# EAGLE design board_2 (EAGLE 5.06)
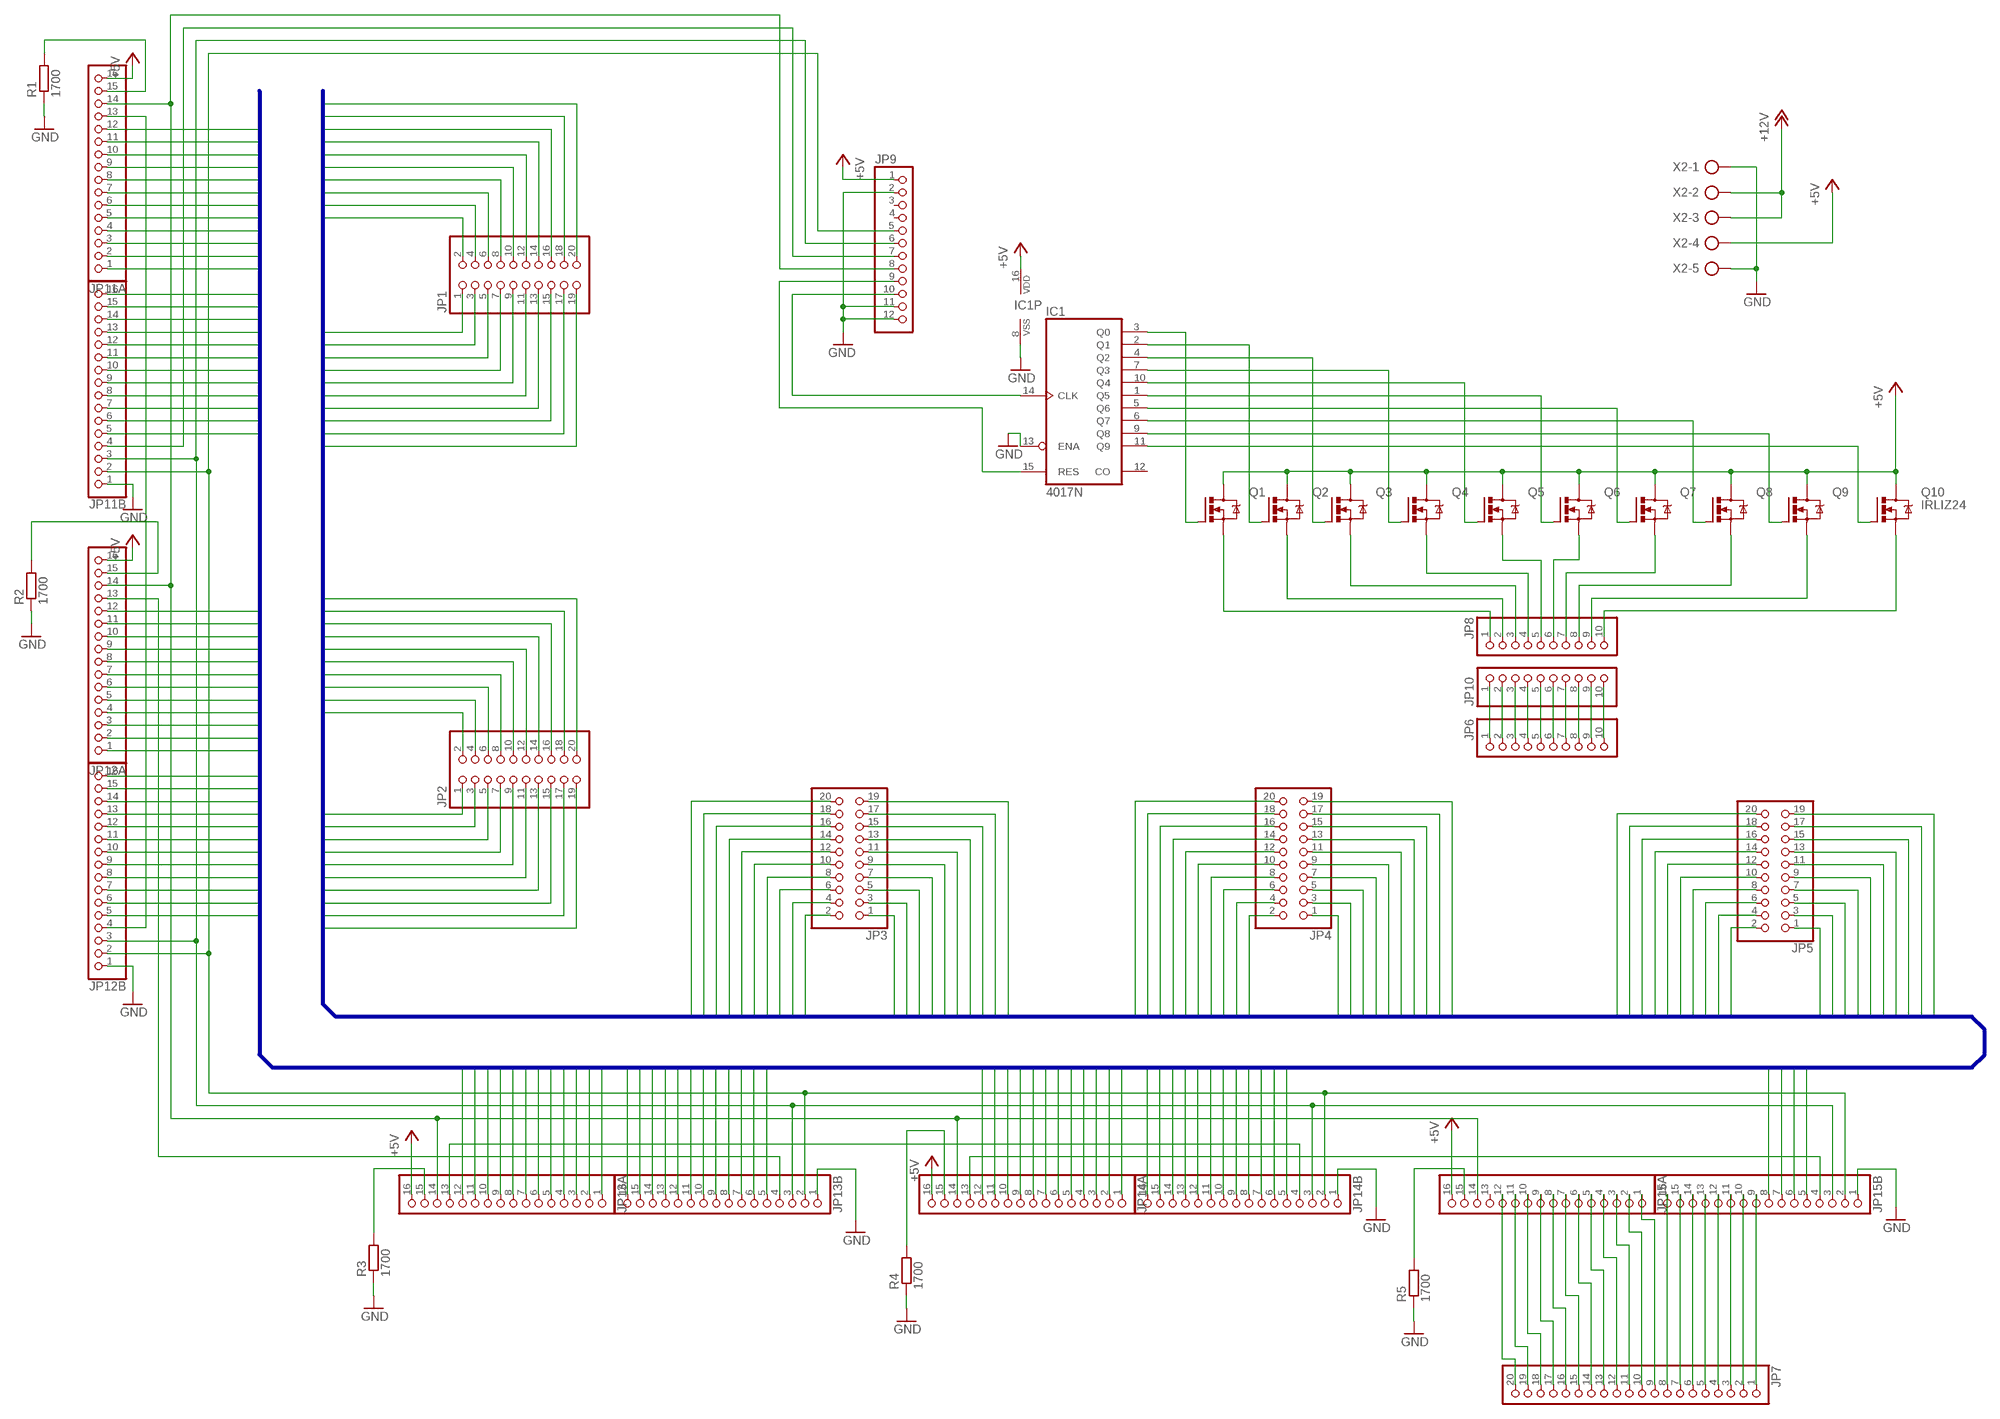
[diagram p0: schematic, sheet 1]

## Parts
IC1  4017N  [DIL16]
JP1  PINHD-2X10  [2X10]
JP2  PINHD-2X10  [2X10]
JP3  PINHD-2X10  [2X10]
JP4  PINHD-2X10  [2X10]
JP5  PINHD-2X10  [2X10]
JP6  PINHD-1X10  [1X10]
JP7  PINHD-1X20  [1X20]
JP8  PINHD-1X10  [1X10]
JP9  PINHD-1X12  [1X12]
JP10  PINHD-1X10  [1X10]
JP11A  PINHD-1X16  [1X16]
JP11B  PINHD-1X16  [1X16]
JP12A  PINHD-1X16  [1X16]
JP12B  PINHD-1X16  [1X16]
JP13A  PINHD-1X16  [1X16]
JP13B  PINHD-1X16  [1X16]
JP14A  PINHD-1X16  [1X16]
JP14B  PINHD-1X16  [1X16]
JP15A  PINHD-1X16  [1X16]
JP15B  PINHD-1X16  [1X16]
Q1  IRF520  [TO220BV]
Q2  IRF520  [TO220BV]
Q3  IRF520  [TO220BV]
Q4  IRF520  [TO220BV]
Q5  IRF520  [TO220BV]
Q6  IRF520  [TO220BV]
Q7  IRF520  [TO220BV]
Q8  IRF520  [TO220BV]
Q9  IRF520  [TO220BV]
Q10  IRLIZ24  IRF520  [TO220BV]
R1  1700  R-EU_0207/7  [0207/7]
R2  1700  R-EU_0207/7  [0207/7]
R3  1700  R-EU_0207/7  [0207/7]
R4  1700  R-EU_0207/7  [0207/7]
R5  1700  R-EU_0207/7  [0207/7]
X2  AK300/5  [AK300/5]

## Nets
+5V: IC1.16(VDD) JP9.1 JP11A.16 JP12A.16 JP13A.16 JP14A.16 JP15A.16 Q1.D Q2.D Q3.D Q4.D Q5.D Q6.D Q7.D Q8.D Q9.D Q10.D X2.4
+12V: X2.2 X2.3
BLANK: JP9.5 JP11B.2 JP12B.2 JP13B.2 JP14B.2 JP15B.2
CLK: JP9.6 JP11B.3 JP12B.3 JP13B.3 JP14B.3 JP15B.3
COLUMN1: JP1.2 JP11B.5
COLUMN2: JP1.4 JP11B.6
COLUMN3: JP1.6 JP11B.7
COLUMN4: JP1.8 JP11B.8
COLUMN5: JP1.10 JP11B.9
COLUMN6: JP1.12 JP11B.10
COLUMN7: JP1.14 JP11B.11
COLUMN8: JP1.16 JP11B.12
COLUMN9: JP1.18 JP11B.13
COLUMN10: JP1.20 JP11B.14
COLUMN11: JP1.1 JP11B.15
COLUMN12: JP1.3 JP11B.16
COLUMN13: JP1.5 JP11A.1
COLUMN14: JP1.7 JP11A.2
COLUMN15: JP1.9 JP11A.3
COLUMN16: JP1.11 JP11A.4
COLUMN17: JP1.13 JP11A.5
COLUMN18: JP1.15 JP11A.6
COLUMN19: JP1.17 JP11A.7
COLUMN20: JP1.19 JP11A.8
COLUMN21: JP2.2 JP11A.9
COLUMN22: JP2.4 JP11A.10
COLUMN23: JP2.6 JP11A.11
COLUMN24: JP2.8 JP11A.12
COLUMN25: JP2.10 JP12B.5
COLUMN26: JP2.12 JP12B.6
COLUMN27: JP2.14 JP12B.7
COLUMN28: JP2.16 JP12B.8
COLUMN29: JP2.18 JP12B.9
COLUMN30: JP2.20 JP12B.10
COLUMN31: JP2.1 JP12B.11
COLUMN32: JP2.3 JP12B.12
COLUMN33: JP2.5 JP12B.13
COLUMN34: JP2.7 JP12B.14
COLUMN35: JP2.9 JP12B.15
COLUMN36: JP2.11 JP12B.16
COLUMN37: JP2.13 JP12A.1
COLUMN38: JP2.15 JP12A.2
COLUMN39: JP2.17 JP12A.3
COLUMN40: JP2.19 JP12A.4
COLUMN41: JP3.2 JP12A.5
COLUMN42: JP3.4 JP12A.6
COLUMN43: JP3.6 JP12A.7
COLUMN44: JP3.8 JP12A.8
COLUMN45: JP3.10 JP12A.9
COLUMN46: JP3.12 JP12A.10
COLUMN47: JP3.14 JP12A.11
COLUMN48: JP3.16 JP12A.12
COLUMN49: JP3.18 JP13B.5
COLUMN50: JP3.20 JP13B.6
COLUMN51: JP3.1 JP13B.7
COLUMN52: JP3.3 JP13B.8
COLUMN53: JP3.5 JP13B.9
COLUMN54: JP3.7 JP13B.10
COLUMN55: JP3.9 JP13B.11
COLUMN56: JP3.11 JP13B.12
COLUMN57: JP3.13 JP13B.13
COLUMN58: JP3.15 JP13B.14
COLUMN59: JP3.17 JP13B.15
COLUMN60: JP3.19 JP13B.16
COLUMN61: JP4.2 JP13A.1
COLUMN62: JP4.4 JP13A.2
COLUMN63: JP4.6 JP13A.3
COLUMN64: JP4.8 JP13A.4
COLUMN65: JP4.10 JP13A.5
COLUMN66: JP4.12 JP13A.6
COLUMN67: JP4.14 JP13A.7
COLUMN68: JP4.16 JP13A.8
COLUMN69: JP4.18 JP13A.9
COLUMN70: JP4.20 JP13A.10
COLUMN71: JP4.1 JP13A.11
COLUMN72: JP4.3 JP13A.12
COLUMN73: JP4.5 JP14B.5
COLUMN74: JP4.7 JP14B.6
COLUMN75: JP4.9 JP14B.7
COLUMN76: JP4.11 JP14B.8
COLUMN77: JP4.13 JP14B.9
COLUMN78: JP4.15 JP14B.10
COLUMN79: JP4.17 JP14B.11
COLUMN80: JP4.19 JP14B.12
COLUMN81: JP5.2 JP14B.13
COLUMN82: JP5.4 JP14B.14
COLUMN83: JP5.6 JP14B.15
COLUMN84: JP5.8 JP14B.16
COLUMN85: JP5.10 JP14A.1
COLUMN86: JP5.12 JP14A.2
COLUMN87: JP5.14 JP14A.3
COLUMN88: JP5.16 JP14A.4
COLUMN89: JP5.18 JP14A.5
COLUMN90: JP5.20 JP14A.6
COLUMN91: JP5.1 JP14A.7
COLUMN92: JP5.3 JP14A.8
COLUMN93: JP5.5 JP14A.9
COLUMN94: JP5.7 JP14A.10
COLUMN95: JP5.9 JP14A.11
COLUMN96: JP5.11 JP14A.12
COLUMN97: JP5.13 JP15B.5
COLUMN98: JP5.15 JP15B.6
COLUMN99: JP5.17 JP15B.7
COLUMN100: JP5.19 JP15B.8
GND: IC1.8(VSS) IC1.13(ENA) JP9.2 JP9.11 JP9.12 JP11B.1 JP12B.1 JP13B.1 JP14B.1 JP15B.1 R1.1 R2.1 R3.1 R4.1 R5.1 X2.1 X2.5
N$1: JP11A.13 JP12B.4
N$2: JP12A.13 JP13B.4
N$3: JP13A.13 JP14B.4
N$4: JP14A.13 JP15B.4
N$5: JP8.1 Q1.S
N$6: JP8.2 Q2.S
N$7: JP8.3 Q3.S
N$8: JP8.4 Q4.S
N$9: JP8.5 Q5.S
N$10: JP8.6 Q6.S
N$11: IC1.14(CLK) JP9.10
N$12: JP8.7 Q7.S
N$13: JP8.8 Q8.S
N$14: JP8.9 Q9.S
N$15: JP8.10 Q10.S
N$16: IC1.3(Q0) Q1.G
N$17: IC1.2(Q1) Q2.G
N$18: IC1.4(Q2) Q3.G
N$19: IC1.7(Q3) Q4.G
N$20: IC1.10(Q4) Q5.G
N$21: IC1.1(Q5) Q6.G
N$22: IC1.5(Q6) Q7.G
N$23: IC1.6(Q7) Q8.G
N$24: IC1.9(Q8) Q9.G
N$25: IC1.11(Q9) Q10.G
N$26: JP7.1 JP15B.9
N$27: JP9.7 JP11B.4
N$28: JP7.2 JP15B.10
N$29: JP7.3 JP15B.11
N$30: JP11A.15 R1.2
N$31: JP12A.15 R2.2
N$32: JP13A.15 R3.2
N$33: JP14A.15 R4.2
N$34: JP15A.15 R5.2
N$35: JP7.4 JP15B.12
N$36: JP7.5 JP15B.13
N$37: JP7.6 JP15B.14
N$38: IC1.15(RES) JP9.9
N$39: JP7.7 JP15B.15
N$40: JP7.8 JP15B.16
N$41: JP7.9 JP15A.1
N$42: JP7.10 JP15A.2
N$43: JP7.11 JP15A.3
N$44: JP7.12 JP15A.4
N$45: JP7.13 JP15A.5
N$46: JP7.14 JP15A.6
N$47: JP7.15 JP15A.7
N$48: JP7.16 JP15A.8
N$49: JP7.17 JP15A.9
N$50: JP7.18 JP15A.10
N$51: JP7.19 JP15A.11
N$52: JP7.20 JP15A.12
N$53: JP6.1 JP10.1
N$54: JP6.2 JP10.2
N$55: JP6.3 JP10.3
N$56: JP6.4 JP10.4
N$57: JP6.5 JP10.5
N$58: JP6.6 JP10.6
N$59: JP6.7 JP10.7
N$60: JP6.8 JP10.8
N$61: JP6.9 JP10.9
N$62: JP6.10 JP10.10
XLAT: JP9.8 JP11A.14 JP12A.14 JP13A.14 JP14A.14 JP15A.14
Unconnected: IC1.12(CO) JP9.3 JP9.4 JP15A.13

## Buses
COLUMN[1..100]

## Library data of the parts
IC1 = 40xx:4017: COUNTER/DIVIDER
JP1-JP5 = pinhead:PINHD-2X10: PIN HEADER
JP6 JP8 JP10 = pinhead:PINHD-1X10: PIN HEADER
JP7 = pinhead:PINHD-1X20: PIN HEADER
JP9 = pinhead:PINHD-1X12: PIN HEADER
JP11A JP11B JP12A JP12B JP13A JP13B JP14A JP14B JP15A JP15B = pinhead:PINHD-1X16: PIN HEADER
Q1-Q10 = transistor-power:IRF520: HEXFET Power MOSFET
R1-R5 = rcl:R-EU_: RESISTOR, European symbol
X2 = con-ptr500:AK300/5: CONNECTOR

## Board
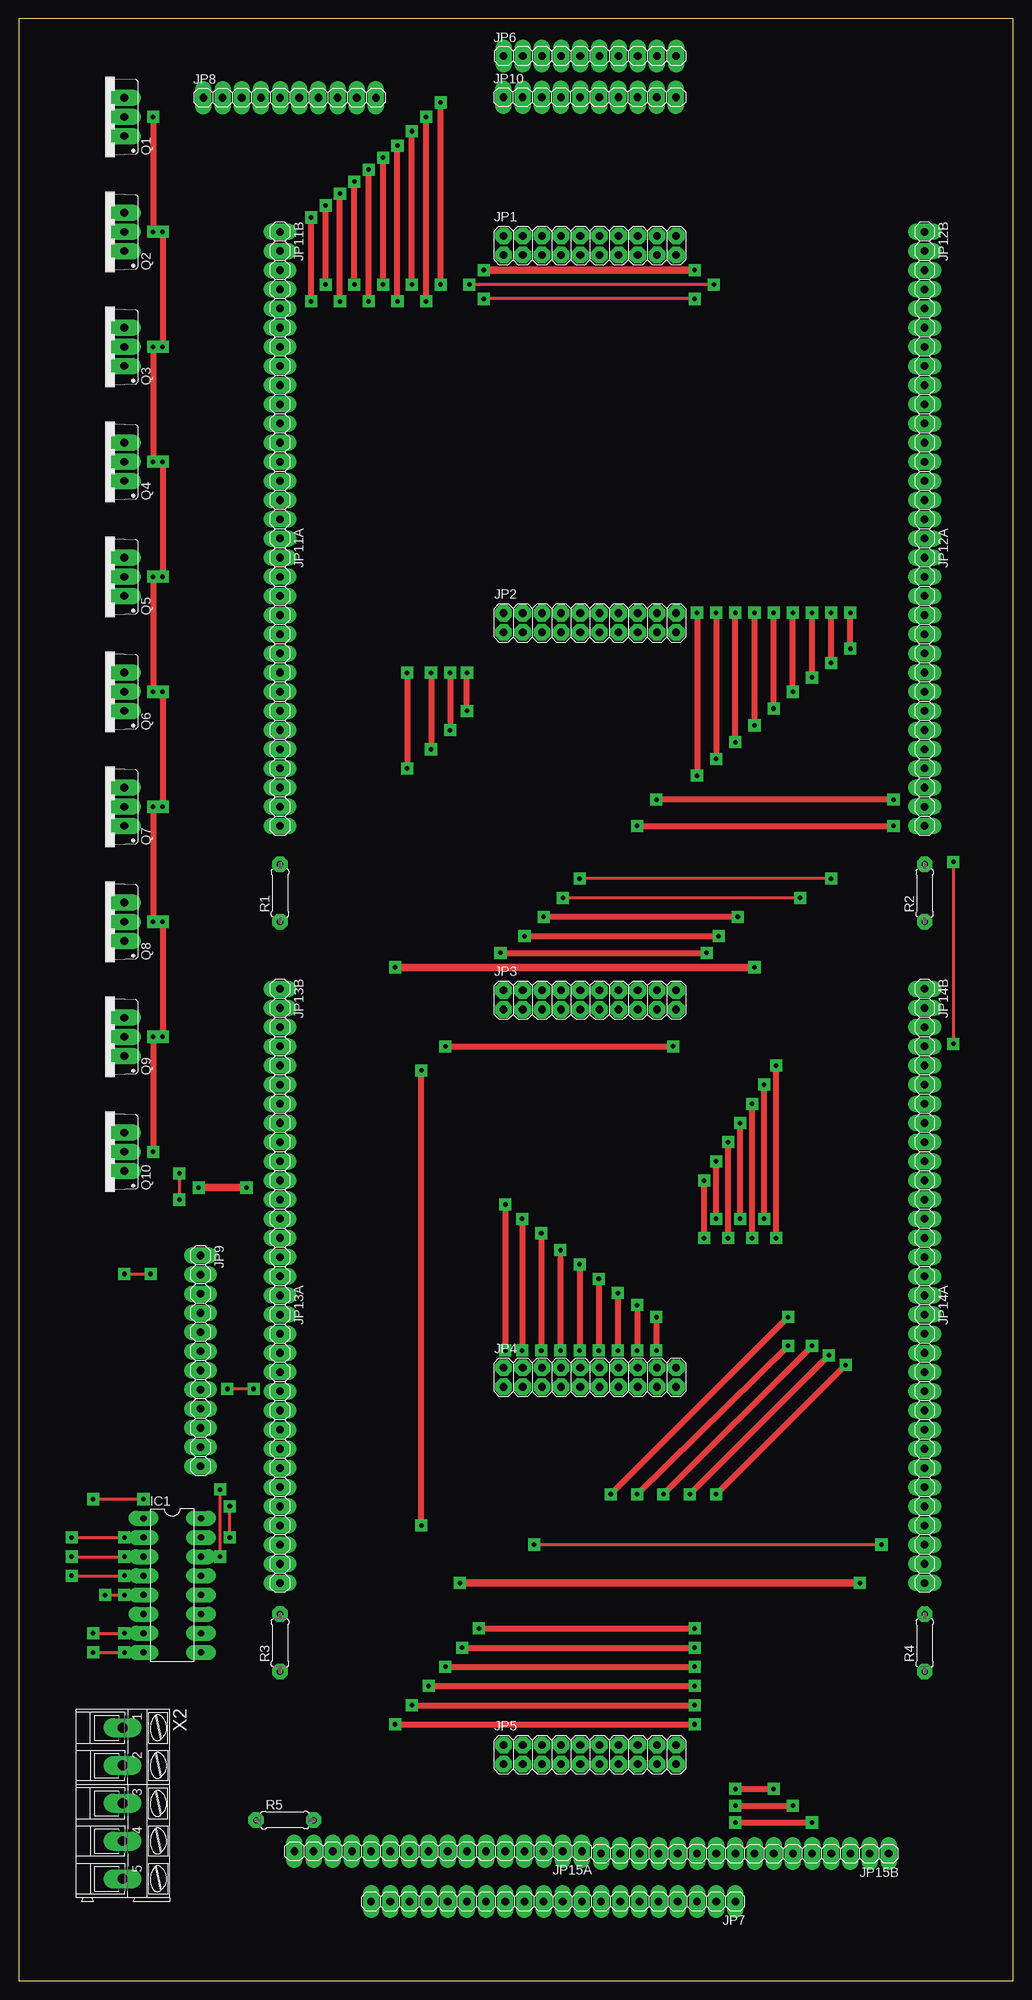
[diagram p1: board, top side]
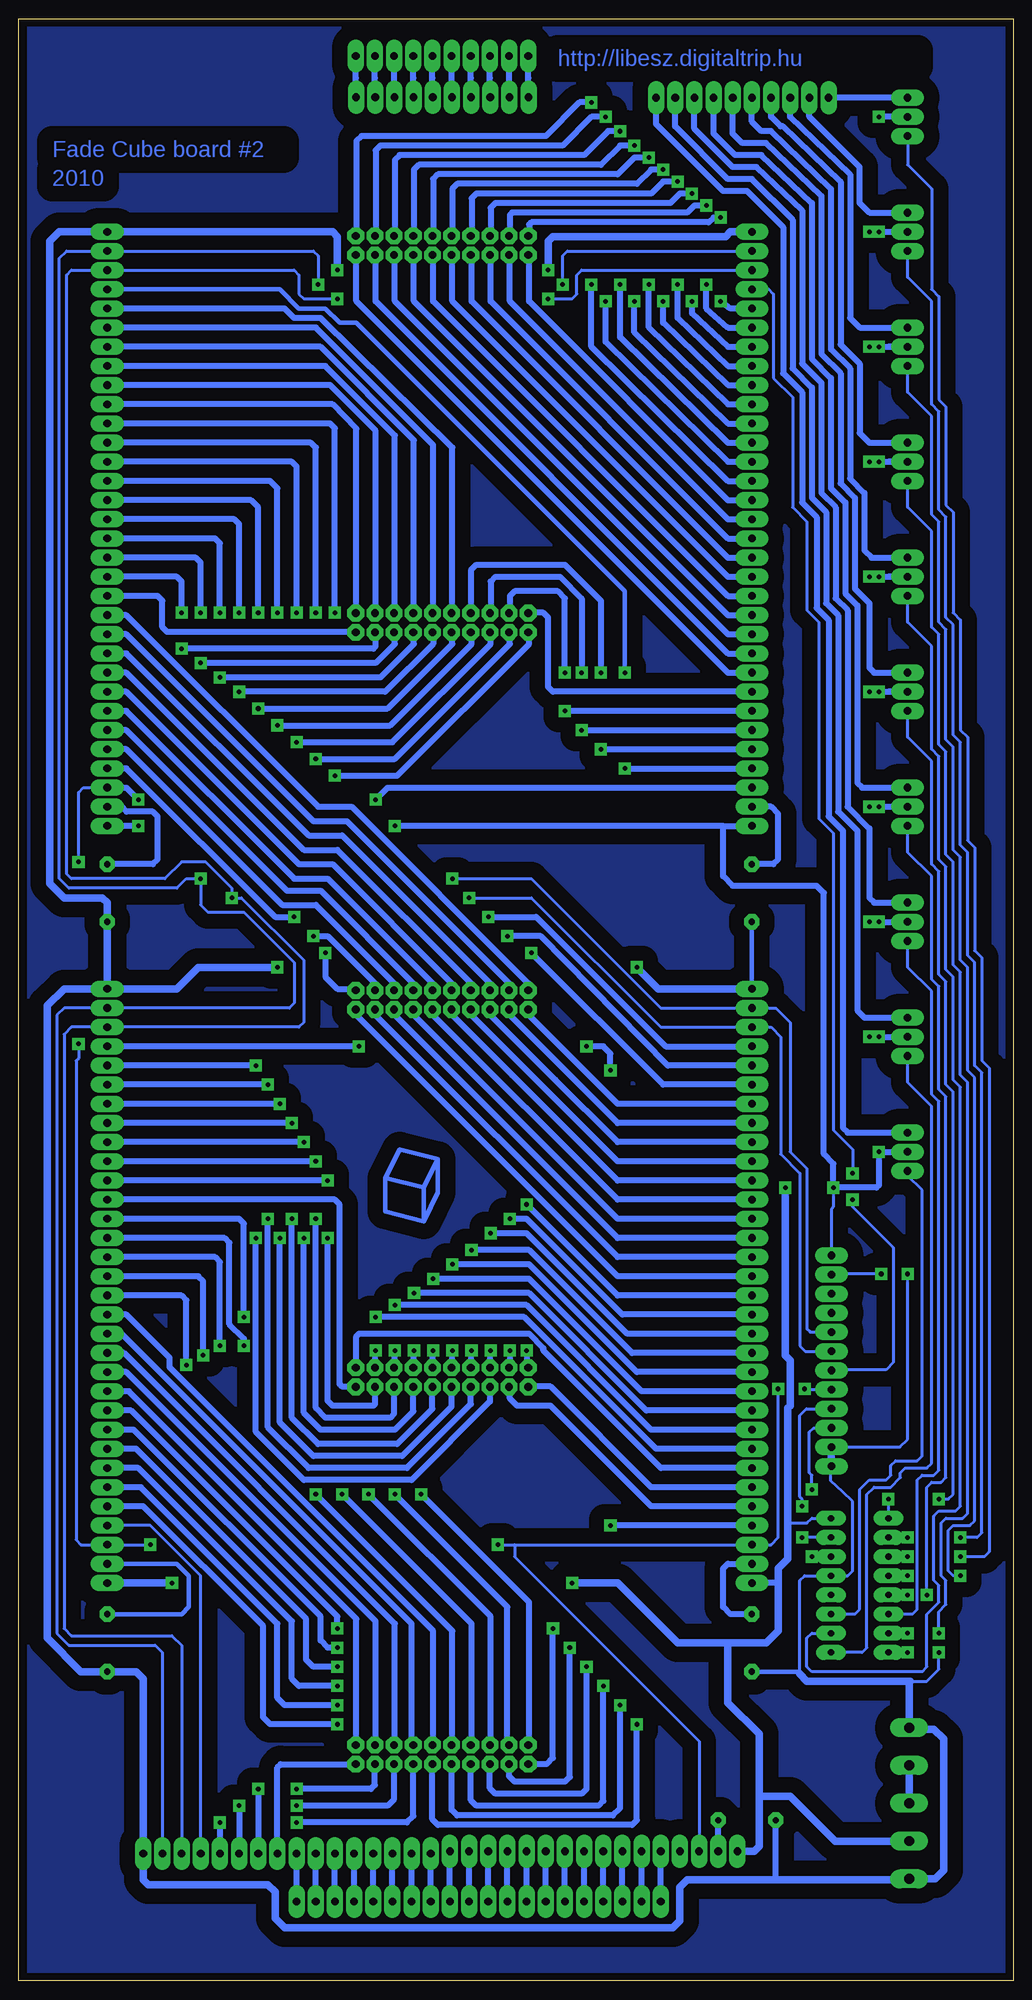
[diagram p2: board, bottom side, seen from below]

Size 131.73 x 260 mm. Coordinates in mm from the lower left corner, seen from the top.
Outline: 0,0 131.73,0 131.73,260 0,260 0,0
Copper layers (1*16): Top 0.035mm / dielectric 1.5mm / Bottom 0.035mm
Design rules "hobby *": minimum track width 0.8mm, minimum drill 0.8mm, track to track 80mil, track to pad 80mil, pad to pad 80mil, via to via 80mil, smd to smd 8mil, copper to edge 40mil, drill to drill 8mil, minimum pad ring 0.6mm, minimum via ring 0.5mm, stop-mask expansion 4mil, vias tented up to drill 0mil, thermal gap 10mil

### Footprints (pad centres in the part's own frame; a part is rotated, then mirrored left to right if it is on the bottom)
DIL16 = drill 0.813 long: 1 -8.89,-3.81; 2 -6.35,-3.81; 3 -3.81,-3.81; 4 -1.27,-3.81; 5 1.27,-3.81; 6 3.81,-3.81; 7 6.35,-3.81; 8 8.89,-3.81; 9 8.89,3.81; 10 6.35,3.81; 11 3.81,3.81; 12 1.27,3.81; 13 -1.27,3.81; 14 -3.81,3.81; 15 -6.35,3.81; 16 -8.89,3.81
2X10 = drill 1.016 octagon: 1 -11.43,-1.27; 2 -11.43,1.27; 3 -8.89,-1.27; 4 -8.89,1.27; 5 -6.35,-1.27; 6 -6.35,1.27; 7 -3.81,-1.27; 8 -3.81,1.27; 9 -1.27,-1.27; 10 -1.27,1.27; 11 1.27,-1.27; 12 1.27,1.27; 13 3.81,-1.27; 14 3.81,1.27; 15 6.35,-1.27; 16 6.35,1.27; 17 8.89,-1.27; 18 8.89,1.27; 19 11.43,-1.27; 20 11.43,1.27
1X10 = drill 1.016 long: 1 -11.43,0; 2 -8.89,0; 3 -6.35,0; 4 -3.81,0; 5 -1.27,0; 6 1.27,0; 7 3.81,0; 8 6.35,0; 9 8.89,0; 10 11.43,0
1X20 = drill 1.016 long: 1 -24.13,0; 2 -21.59,0; 3 -19.05,0; 4 -16.51,0; 5 -13.97,0; 6 -11.43,0; 7 -8.89,0; 8 -6.35,0; 9 -3.81,0; 10 -1.27,0; 11 1.27,0; 12 3.81,0; 13 6.35,0; 14 8.89,0; 15 11.43,0; 16 13.97,0; 17 16.51,0; 18 19.05,0; 19 21.59,0; 20 24.13,0
1X12 = drill 1.016 long: 1 -13.97,0; 2 -11.43,0; 3 -8.89,0; 4 -6.35,0; 5 -3.81,0; 6 -1.27,0; 7 1.27,0; 8 3.81,0; 9 6.35,0; 10 8.89,0; 11 11.43,0; 12 13.97,0
1X16 = drill 1.016 long: 1 -19.05,0; 2 -16.51,0; 3 -13.97,0; 4 -11.43,0; 5 -8.89,0; 6 -6.35,0; 7 -3.81,0; 8 -1.27,0; 9 1.27,0; 10 3.81,0; 11 6.35,0; 12 8.89,0; 13 11.43,0; 14 13.97,0; 15 16.51,0; 16 19.05,0
TO220BV = drill 1.016 long: D 0,-2.54; G -2.54,-2.54; S 2.54,-2.54
0207/7 = drill 0.813 octagon: 1 -3.81,0; 2 3.81,0
AK300/5 = drill 1.321 long: 1 -10.008,0; 2 -5.004,0; 3 0,0; 4 5.004,0; 5 10.008,0

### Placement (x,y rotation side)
IC1  20.32,52.39 270 top
JP1  75.66,229.97 0 top
JP2  75.66,179.97 0 top
JP3  75.66,129.97 0 top
JP4  75.66,79.97 0 top
JP5  75.66,29.97 0 top
JP6  75.66,255.08 0 top
JP7  70.8,10.48 180 top
JP8  35.88,249.56 0 top
JP9  24.06,82.15 270 top
JP10  75.63,249.62 0 top
JP11A  34.61,172.09 270 top
JP11B  34.61,212.72 270 top
JP12A  120.02,172.09 270 top
JP12B  120.02,212.72 270 top
JP13A  34.61,71.75 270 top
JP13B  34.61,112.39 270 top
JP14A  120.02,71.75 270 top
JP14B  120.02,112.39 270 top
JP15A  55.56,17.14 180 top
JP15B  96.2,16.83 180 top
Q1  11.43,247.01 90 top
Q2  11.43,231.78 90 top
Q3  11.43,216.53 90 top
Q4  11.43,201.29 90 top
Q5  11.43,186.06 90 top
Q6  11.43,170.81 90 top
Q7  11.43,155.57 90 top
Q8  11.43,140.34 90 top
Q9  11.43,125.09 90 top
Q10  11.43,109.86 90 top
R1  34.61,144.15 90 top
R2  120.02,144.15 90 top
R3  34.61,44.77 90 top
R4  120.02,44.77 90 top
R5  35.24,21.27 0 top
U$1  [CUBE_LOGO]  76.2,108.9 0 top
X2  13.76,23.5 270 top

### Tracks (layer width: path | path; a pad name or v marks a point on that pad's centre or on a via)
+5V  (via drill 0.6, 0.6 pad 0.25)
  Top 0.813: v17.78,247.01 v17.78,231.78 | v19.05,231.78 v19.05,216.53 | v17.78,216.53 v17.78,201.29 | v19.05,201.29 v19.05,186.06 | v17.78,186.06 v17.78,170.81 | v19.05,170.81 v19.05,155.57 | v17.78,155.57 v17.78,140.34 | v19.05,140.34 v19.05,125.09 | v17.78,125.09 v17.78,109.86 | v81.92,153.03 v115.89,153.03 | v23.81,105.09 23.9,105.01
  Top 1.016: v23.81,105.09 v30.16,105.09 | v58.42,52.7 v111.44,52.7
  Bottom 0.406: IC1.16 26.67,61.28 27.3,60.64 29.84,60.64 | JP9.1 24.06,102.17 23.81,102.55 v23.81,105.09
  Bottom 0.813: Q1.D v17.78,247.01 | 16.51,170.81 Q6.D v17.78,170.81 v19.05,170.81 | 16.51,186.06 Q5.D v17.78,186.06 v19.05,186.06 | 16.51,201.29 Q4.D v17.78,201.29 v19.05,201.29 | 16.51,216.53 Q3.D v17.78,216.53 v19.05,216.53 | Q2.D v17.78,231.78 v19.05,231.78 | v19.05,155.57 v17.78,155.57 Q7.D | Q8.D v17.78,140.34 v19.05,140.34 | v19.05,125.09 v17.78,125.09 Q9.D | Q10.D v17.78,109.86 17.78,105.41 18.1,105.09 v23.81,105.09 23.81,108.27 25.08,109.54 25.08,144.15 26.04,145.1 37.15,145.1 38.42,146.37 38.42,153.03 | 38.42,153.03 v81.92,153.03 | v115.89,153.03 JP12A.16 | 38.42,153.03 JP11A.16 | 31.11,53.02 31.11,52.7 JP13A.16
  Bottom 1.016: X2.4 23.58,18.5 29.53,24.45 33.66,24.45 | 33.66,24.45 33.66,17.78 34.29,17.14 JP15A.16 | 33.66,24.45 33.66,32.7 37.78,36.83 37.78,44.77 | v30.16,105.09 30.16,82.87 29.53,82.23 29.53,76.2 29.84,75.88 29.84,60.64 29.84,55.88 31.11,54.61 31.11,53.02 31.11,46.35 32.7,44.77 37.78,44.77 | v111.44,52.7 JP14A.16 | v58.42,52.7 52.39,52.7 44.45,44.77 37.78,44.77
+12V
  Bottom 1.016: X2.3 X2.2
BLANK  (via drill 0.6 pad 0.25)
  Top 0.406: v92.08,224.79 v59.69,224.79 | v107.63,146.05 v74.3,146.05
  Bottom 0.406: JP11B.2 59.05,229.24 59.69,228.6 v59.69,224.79 | v92.08,224.79 92.08,228.6 92.71,229.24 JP12B.2 125.41,229.24 126.36,228.28 126.36,146.05 125.09,144.78 110.81,144.78 109.54,146.05 v107.63,146.05 107.63,142.56 106.68,141.6 101.92,141.6 95.25,134.94 95.25,129.54 95.89,128.91 JP14B.2 125.73,128.91 126.68,127.95 126.68,46.04 125.09,44.45 113.67,44.45 112.71,43.5 JP15B.2 | v74.3,146.05 63.82,146.05 46.67,128.91 JP13B.2 31.43,128.91 29.53,127 29.53,109.86 27.3,107.63 27.3,86.36 26.9,85.96 JP9.5
CLK  (via drill 0.6 pad 0.25)
  Top 0.406: v89.53,222.88 v61.59,222.88 | v103.5,143.51 v72.07,143.51
  Bottom 0.406: JP11B.3 57.15,226.69 57.78,226.06 57.78,223.52 58.42,222.88 v61.59,222.88 | v89.53,222.88 93.98,222.88 94.61,223.52 94.61,226.06 95.25,226.69 JP12B.3 124.78,226.69 125.41,226.06 125.41,146.69 124.78,146.05 112.39,146.05 110.17,148.27 107,148.27 103.5,144.78 v103.5,143.51 102.23,143.51 93.98,135.25 93.98,127 94.61,126.36 JP14B.3 124.78,126.36 125.73,125.41 125.73,46.67 124.78,45.72 111.44,45.72 110.17,44.45 JP15B.3 | v72.07,143.51 63.82,143.51 46.67,126.36 JP13B.3 32.07,126.36 30.8,125.09 30.8,109.54 28.26,107 28.26,84.14 27.54,83.42 JP9.6
COLUMN1  (via drill 0.6, 0.6 pad 0.81)
  Top 0.813: v38.73,222.57 v38.73,233.68
  Bottom 0.813: JP11B.5 37.47,221.62 v38.73,222.57 | JP1.2 64.14,231.33 64.14,232.73 63.82,233.04 40.32,233.04 39.69,233.68 v38.73,233.68
COLUMN2  (via drill 0.6)
  Top 0.813: v40.64,224.79 v40.64,235.27
  Bottom 0.813: JP11B.6 37.78,219.07 40.64,221.62 v40.64,224.79 | v40.64,235.27 42.23,235.27 43.18,234.31 66.36,234.31 66.67,234 66.67,231.33 JP1.4
COLUMN3  (via drill 0.6)
  Top 0.813: v42.55,222.57 v42.55,236.85
  Bottom 0.813: JP11B.7 37.78,216.53 42.55,220.98 v42.55,222.57 | v42.55,236.85 44.13,236.85 45.4,235.59 68.58,235.59 69.22,234.95 69.22,231.33 JP1.6
COLUMN4  (via drill 0.6)
  Top 0.813: v44.45,224.79 v44.45,238.44
  Bottom 0.813: JP11B.8 37.78,214 44.45,220.34 v44.45,224.79 | v44.45,238.44 46.35,238.44 47.94,236.85 71.12,236.85 71.75,236.22 71.75,231.33 JP1.8
COLUMN5  (via drill 0.6 pad 0.25)
  Top 0.813: v46.35,222.57 v46.35,240.03
  Bottom 0.813: JP11B.9 37.78,211.46 46.35,219.71 v46.35,222.57 | v46.35,240.03 47.94,240.03 49.85,238.12 73.66,238.12 74.3,237.49 74.3,231.33 JP1.10
COLUMN6  (via drill 0.6 pad 0.25)
  Top 0.813: v48.26,224.79 v48.26,241.62
  Bottom 0.813: JP11B.10 37.78,208.91 48.26,219.07 v48.26,224.79 | v48.26,241.62 50.16,241.62 52.39,239.4 76.2,239.4 76.83,238.76 76.83,231.33 JP1.12
COLUMN7  (via drill 0.6 pad 0.25)
  Top 0.813: v50.16,222.57 v50.16,243.21
  Bottom 0.813: JP11B.11 37.78,206.38 50.16,218.44 v50.16,222.57 | v50.16,243.21 52.07,243.21 54.61,240.66 78.74,240.66 79.38,240.03 79.38,231.33 JP1.14
COLUMN8  (via drill 0.6 pad 0.25)
  Top 0.813: v52.07,224.79 v52.07,245.11
  Bottom 0.813: JP11B.12 37.78,203.84 52.07,217.81 v52.07,224.79 | 82.23,231.46 JP1.16 81.92,231.33 81.92,241.3 81.28,241.94 56.83,241.94 53.66,245.11 v52.07,245.11
COLUMN9  (via drill 0.6 pad 0.25)
  Top 0.813: v53.98,222.57 v53.98,247.01
  Bottom 0.813: JP11B.13 37.78,201.29 53.98,217.17 v53.98,222.57 | v53.98,247.01 55.88,247.01 59.69,243.21 83.82,243.21 84.45,242.57 84.45,231.33 JP1.18
COLUMN10  (via drill 0.6 pad 0.81)
  Top 0.813: v55.88,224.79 v55.88,248.92
  Bottom 0.813: JP11B.14 37.78,198.75 55.88,216.53 v55.88,224.79 | v55.88,248.92 57.47,248.92 61.91,244.47 86.36,244.47 87,243.84 87,231.33 JP1.20
COLUMN11
  Bottom 0.813: JP11B.15 37.78,196.22 64.14,222.57 64.14,228.6 JP1.1
COLUMN12
  Bottom 0.813: JP11B.16 37.78,193.68 66.67,222.57 66.67,228.6 JP1.3
COLUMN13
  Bottom 0.813: JP11A.1 37.78,191.13 69.22,222.57 69.22,228.6 JP1.5
COLUMN14
  Bottom 0.813: JP11A.2 37.78,188.59 71.75,222.57 71.75,228.6 JP1.7
COLUMN15
  Bottom 0.813: JP11A.3 37.78,186.06 74.3,222.57 74.3,228.6 JP1.9
COLUMN16
  Bottom 0.813: JP11A.4 37.78,183.51 76.83,222.57 76.83,228.6 JP1.11
COLUMN17
  Bottom 0.813: JP11A.5 37.78,180.97 79.38,222.57 79.38,228.6 JP1.13
COLUMN18
  Bottom 0.813: JP11A.6 37.78,178.44 81.92,222.57 81.92,228.6 JP1.15
COLUMN19
  Bottom 0.813: JP11A.7 37.78,175.9 84.45,222.57 84.45,228.6 JP1.17
COLUMN20
  Bottom 0.813: JP11A.8 37.78,173.35 87,222.57 87,228.6 JP1.19
COLUMN21
  Bottom 0.813: JP11A.9 60.96,170.81 61.59,171.45 61.59,180.66 62.23,181.29 64.17,181.29 JP2.2
COLUMN22  (via drill 0.6 pad 0.81)
  Top 0.813: v59.37,168.28 v59.37,173.35
  Bottom 0.813: JP11A.10 v59.37,168.28 | v59.37,173.35 59.37,183.2 60.33,184.15 66.04,184.15 66.67,183.51 66.67,181.33 JP2.4
COLUMN23  (via drill 0.6 pad 0.81)
  Top 0.813: v57.15,173.35 v57.15,165.74
  Bottom 0.813: v57.15,165.74 JP11A.11 | v57.15,173.35 57.15,183.2 60.01,186.06 68.58,186.06 69.22,185.42 69.22,181.33 JP2.6
COLUMN24  (via drill 0.6 pad 0.25)
  Top 0.813: v54.61,173.35 v54.61,163.19
  Bottom 0.813: JP2.8 71.85,186.91 71.12,187.64 59.37,187.64 54.61,182.88 v54.61,173.35 | v54.61,163.19 JP11A.12
COLUMN25
  Bottom 0.813: JP12B.5 96.52,221.62 95.25,220.34 91.76,220.34 74.3,203.2 74.3,181.33 JP2.10
COLUMN26
  Bottom 0.813: JP12B.6 92.39,219.07 76.83,203.52 76.83,181.33 JP2.12
COLUMN27
  Bottom 0.813: JP12B.7 91.76,216.53 79.38,204.15 79.38,181.33 JP2.14
COLUMN28
  Bottom 0.813: JP12B.8 91.12,214 81.92,204.79 81.92,181.33 JP2.16
COLUMN29
  Bottom 0.813: JP12B.9 90.49,211.46 84.45,205.42 84.45,181.33 JP2.18
COLUMN30
  Bottom 0.813: JP12B.10 90.17,208.91 87,205.68 87,181.33 JP2.20
COLUMN31  (via drill 0.6 pad 0.81)
  Top 0.813: v89.85,181.29 v89.85,159.7
  Bottom 0.813: JP12B.11 90.49,206.38 89.85,205.74 v89.85,181.29 | v89.85,159.7 81.6,159.7 64.14,177.16 64.14,178.6 JP2.1
COLUMN32  (via drill 0.6 pad 0.81)
  Top 0.813: v92.39,181.29 v92.39,161.93
  Bottom 0.813: JP12B.12 93.03,203.84 92.39,203.2 v92.39,181.29 | v92.39,161.93 81.92,161.93 66.67,177.16 66.67,178.6 JP2.3
COLUMN33  (via drill 0.6 pad 0.81)
  Top 0.813: v94.93,164.15 v94.93,181.29
  Bottom 0.813: JP12B.13 95.57,201.29 94.93,200.66 v94.93,181.29 | v94.93,164.15 82.23,164.15 69.22,177.16 69.22,178.6 JP2.5
COLUMN34  (via drill 0.6 pad 0.81)
  Top 0.813: v97.47,166.37 v97.47,181.29
  Bottom 0.813: JP12B.14 98.42,198.75 97.47,197.8 v97.47,181.29 | v97.47,166.37 82.55,166.37 71.75,177.16 71.75,178.6 JP2.7
COLUMN35  (via drill 0.6 pad 0.81)
  Top 0.813: v100.01,168.59 v100.01,181.29
  Bottom 0.813: JP12B.15 100.97,196.22 100.01,195.26 v100.01,181.29 | v100.01,168.59 82.87,168.59 74.3,177.16 74.3,178.6 JP2.9
COLUMN36  (via drill 0.6 pad 0.81)
  Top 0.813: v102.55,170.81 v102.55,181.29
  Bottom 0.813: JP12B.16 103.19,193.68 102.55,193.04 v102.55,181.29 | v102.55,170.81 83.19,170.81 76.83,177.16 76.83,178.6 JP2.11
COLUMN37  (via drill 0.6 pad 0.81)
  Top 0.813: v105.09,172.72 v105.09,181.29
  Bottom 0.813: JP12A.1 105.73,191.13 105.09,190.5 v105.09,181.29 | v105.09,172.72 83.82,172.72 79.38,177.16 79.38,178.6 JP2.13
COLUMN38  (via drill 0.6 pad 0.81)
  Top 0.813: v107.63,174.62 v107.63,181.29
  Bottom 0.813: JP12A.2 108.27,188.59 107.63,187.96 v107.63,181.29 | v107.63,174.62 84.45,174.62 81.92,177.16 81.92,178.6 JP2.15
COLUMN39  (via drill 0.6 pad 0.81)
  Top 0.813: v110.17,176.53 v110.17,181.29
  Bottom 0.813: JP12A.3 110.81,186.06 110.17,185.42 v110.17,181.29 | v110.17,176.53 84.77,176.53 84.45,176.85 84.45,178.6 JP2.17
COLUMN40
  Bottom 0.813: JP12A.4 113.35,183.51 112.71,182.88 112.71,179.39 112.08,178.75 87.14,178.75 JP2.19
COLUMN41
  Bottom 0.813: JP3.2 64.23,132.18 87.63,155.57 92.08,155.57 117.47,180.97 JP12A.5
COLUMN42
  Bottom 0.813: JP3.4 66.77,132.18 88.27,153.67 92.71,153.67 117.47,178.44 JP12A.6
COLUMN43
  Bottom 0.813: JP12A.7 117.47,175.9 93.34,151.76 88.9,151.76 69.22,132.08 69.22,131.33 JP3.6
COLUMN44
  Bottom 0.813: JP12A.8 117.47,173.35 93.98,149.86 89.53,149.86 71.75,132.08 71.75,131.33 JP3.8
COLUMN45
  Bottom 0.813: JP12A.9 117.47,170.81 94.61,147.96 90.17,147.96 74.3,132.08 74.3,131.33 JP3.10
COLUMN46
  Bottom 0.813: JP12A.10 117.47,168.28 95.25,146.05 90.81,146.05 76.83,132.08 76.83,131.33 JP3.12
COLUMN47
  Bottom 0.813: JP12A.11 117.47,165.74 96.2,144.46 91.76,144.46 79.38,132.08 79.38,131.33 JP3.14
COLUMN48
  Bottom 0.813: JP12A.12 117.47,163.19 96.84,142.56 92.39,142.56 81.92,132.08 81.92,131.33 JP3.16
COLUMN49  (via drill 0.6 pad 0.25)
  Top 0.813: v66.99,138.43 v92.71,138.43
  Bottom 0.813: JP13B.5 45.72,121.28 62.55,138.43 v66.99,138.43 | v92.71,138.43 90.81,138.43 84.45,132.08 84.45,131.33 JP3.18
COLUMN50  (via drill 0.6 pad 0.25)
  Top 0.813: v63.82,136.21 v91.12,136.21
  Bottom 0.813: JP13B.6 46.35,118.75 v63.82,136.21 | v91.12,136.21 91.12,133.03 89.53,131.44 87.3,131.44 JP3.20
COLUMN51
  Bottom 0.813: JP3.1 64.23,128.05 52.39,116.2 JP13B.7
COLUMN52
  Bottom 0.813: JP3.3 66.77,128.05 52.39,113.67 JP13B.8
COLUMN53
  Bottom 0.813: JP3.5 69.31,128.05 60.96,119.7 | 60.96,119.7 60.64,119.38 | JP13B.9 52.39,111.12 60.96,119.7
COLUMN54
  Bottom 0.813: JP3.7 71.85,128.05 52.39,108.58 JP13B.10
COLUMN55
  Bottom 0.813: JP3.9 74.39,128.05 66.67,120.33 | 66.67,120.33 66.36,120.02 | JP13B.11 52.39,106.05 66.67,120.33
COLUMN56
  Bottom 0.813: JP3.11 76.93,128.05 52.39,103.5 JP13B.12
COLUMN57
  Bottom 0.813: JP3.13 79.47,128.05 52.39,100.97 JP13B.13
COLUMN58
  Bottom 0.813: JP3.15 82.01,128.05 52.39,98.42 JP13B.14
COLUMN59
  Bottom 0.813: JP3.17 84.55,128.05 52.39,95.89 JP13B.15
COLUMN60
  Bottom 0.813: JP3.19 87.09,128.05 52.39,93.34 36.51,93.34 36.2,93.03 35.88,93.03 JP13B.16
COLUMN61  (via drill 0.6 pad 0.81)
  Top 0.813: v64.45,102.87 v64.45,83.5
  Bottom 0.813: JP13A.1 52.39,90.81 v64.45,102.87 | v64.45,83.5 64.45,81.33 JP4.2
COLUMN62  (via drill 0.6 pad 0.81)
  Top 0.813: v66.67,100.97 v66.67,83.5
  Bottom 0.813: JP13A.2 51.75,88.27 64.45,100.97 v66.67,100.97 | v66.67,83.5 66.67,81.33 JP4.4
COLUMN63  (via drill 0.6 pad 0.81)
  Top 0.813: v69.22,99.06 v69.22,83.5
  Bottom 0.813: JP4.6 69.31,83.41 v69.22,83.5 | v69.22,99.06 64.45,99.06 51.12,85.72 JP13A.3
COLUMN64  (via drill 0.6 pad 0.81)
  Top 0.813: v71.75,96.84 v71.75,83.5
  Bottom 0.813: JP4.8 71.85,83.41 v71.75,83.5 | v71.75,96.84 64.14,96.84 50.48,83.19 JP13A.4
COLUMN65  (via drill 0.6 pad 0.81)
  Top 0.813: v74.3,94.93 v74.3,83.5
  Bottom 0.813: JP4.10 74.39,83.41 v74.3,83.5 | v74.3,94.93 64.14,94.93 49.85,80.64 JP13A.5
COLUMN66  (via drill 0.6 pad 0.81)
  Top 0.813: v76.83,93.03 v76.83,83.5
  Bottom 0.813: JP4.12 76.93,83.41 v76.83,83.5 | v76.83,93.03 64.14,93.03 49.21,78.11 JP13A.6
COLUMN67  (via drill 0.6 pad 0.81)
  Top 0.813: v79.38,91.12 v79.38,83.5
  Bottom 0.813: JP4.14 79.47,83.41 v79.38,83.5 | v79.38,91.12 64.14,91.12 48.58,75.56 JP13A.7
COLUMN68  (via drill 0.6 pad 0.81)
  Top 0.813: v81.92,89.53 v81.92,83.5
  Bottom 0.813: JP13A.8 47.94,73.03 64.45,89.53 v81.92,89.53 | JP4.16 82.01,83.41 v81.92,83.5
COLUMN69  (via drill 0.6 pad 0.81)
  Top 0.813: v84.45,87.95 v84.45,83.5
  Bottom 0.813: JP4.18 84.55,83.41 v84.45,83.5 | v84.45,87.95 64.77,87.95 47.31,70.48 JP13A.9
COLUMN70
  Bottom 0.813: JP4.20 87.09,85.31 86.68,85.72 64.14,85.72 62.23,83.82 62.23,83.5 46.67,67.94 JP13A.10
COLUMN71
  Bottom 0.813: JP13A.11 47.94,65.41 61.28,78.74 64.19,78.74 JP4.1
COLUMN72
  Bottom 0.813: JP13A.12 47.94,62.87 61.28,76.2 65.72,76.2 66.67,77.15 66.67,78.6 JP4.3
COLUMN73  (via drill 0.6 pad 0.81)
  Top 0.813: v100.33,98.42 v100.33,121.28
  Bottom 0.813: JP4.5 69.31,76.74 79.69,66.36 93.98,66.36 100.33,72.71 v100.33,98.42 | v100.33,121.28 JP14B.5
COLUMN74  (via drill 0.6 pad 0.81)
  Top 0.813: v98.74,100.97 v98.74,118.75
  Bottom 0.813: JP4.7 71.85,76.42 80.33,67.94 93.34,67.94 98.74,73.34 v98.74,100.97 | v98.74,118.75 JP14B.6
COLUMN75  (via drill 0.6 pad 0.81)
  Top 0.813: v97.16,98.42 v97.16,116.2
  Bottom 0.813: JP4.9 74.39,76.11 80.96,69.53 92.71,69.53 97.16,73.98 v97.16,98.42 | v97.16,116.2 JP14B.7
COLUMN76  (via drill 0.6 pad 0.81)
  Top 0.813: v95.57,100.97 v95.57,113.67
  Bottom 0.813: JP4.11 76.93,75.79 81.6,71.12 92.08,71.12 95.57,74.61 v95.57,100.97 | v95.57,113.67 JP14B.8
COLUMN77  (via drill 0.6 pad 0.81)
  Top 0.813: v93.98,98.42 v93.98,111.12
  Bottom 0.813: JP4.13 79.47,75.47 81.92,73.03 91.76,73.03 93.98,75.25 v93.98,98.42 | v93.98,111.12 JP14B.9
COLUMN78  (via drill 0.6 pad 0.81)
  Top 0.813: v92.39,100.97 v92.39,108.58
  Bottom 0.813: JP4.15 82.01,75.15 82.55,74.61 91.12,74.61 92.39,75.88 v92.39,100.97 | v92.39,108.58 JP14B.10
COLUMN79  (via drill 0.6 pad 0.81)
  Top 0.813: v90.81,98.42 v90.81,106.05
  Bottom 0.813: JP4.17 84.55,76.42 84.77,76.2 90.17,76.2 90.81,76.83 v90.81,98.42 | v90.81,106.05 JP14B.11
COLUMN80
  Bottom 0.813: JP4.19 88.86,78.7 89.22,79.06 89.22,102.87 89.85,103.5 JP14B.12
COLUMN81  (via drill 0.6)
  Top 0.813: v78.42,64.45 v101.92,87.95
  Bottom 0.813: JP14B.13 102.55,100.97 101.92,100.33 v101.92,87.95 | v78.42,64.45 64.14,50.16 64.14,31.33 JP5.2
COLUMN82  (via drill 0.6)
  Top 0.813: v81.92,64.45 v101.92,84.14
  Bottom 0.813: JP14B.14 104.46,98.42 103.82,97.79 103.82,87 101.92,85.09 v101.92,84.14 | v81.92,64.45 66.99,49.53 66.99,31.46 JP5.4
COLUMN83  (via drill 0.6)
  Top 0.813: v85.41,64.45 v105.09,84.14
  Bottom 0.813: JP14B.15 105.73,95.89 105.09,95.25 v105.09,84.14 | v85.41,64.45 69.22,48.26 69.22,31.33 JP5.6
COLUMN84  (via drill 0.6)
  Top 0.813: v88.9,64.45 v107.31,82.87
  Bottom 0.813: JP14B.16 107.95,93.34 107.31,92.71 v107.31,82.87 | v88.9,64.45 71.75,47.31 71.75,31.33 JP5.8
COLUMN85  (via drill 0.6)
  Top 0.813: v92.39,64.45 v109.54,81.6
  Bottom 0.813: JP14A.1 110.17,90.81 109.54,90.17 v109.54,81.6 | v92.39,64.45 74.3,46.35 74.3,31.33 JP5.10
COLUMN86
  Bottom 0.813: JP5.12 76.83,31.33 76.83,46.35 111.76,81.28 111.76,82.55 117.47,88.27 JP14A.2
COLUMN87
  Bottom 0.813: JP14A.3 118.11,85.72 79.69,47.31 79.69,31.46 JP5.14
COLUMN88
  Bottom 0.813: JP14A.4 117.79,83.19 81.92,47.31 81.92,31.33 JP5.16
COLUMN89
  Bottom 0.813: JP14A.5 117.47,80.64 84.45,47.62 84.45,31.33 JP5.18
COLUMN90
  Bottom 0.813: JP14A.6 117.16,78.11 87,47.94 87,31.33 JP5.20
COLUMN91  (via drill 0.6)
  Top 0.813: v60.96,46.67 v89.53,46.67
  Bottom 0.813: JP14A.7 116.84,75.56 89.53,48.26 v89.53,46.67 | JP5.1 61.79,28.7 60.96,29.53 v60.96,46.67
COLUMN92  (via drill 0.6)
  Top 0.813: v58.74,44.13 v89.53,44.13
  Bottom 0.813: JP5.3 66.77,27.08 66.04,26.35 59.37,26.35 58.74,26.99 v58.74,44.13 | v89.53,44.13 90.81,44.13 91.76,45.09 91.76,48.26 116.52,73.03 JP14A.8
COLUMN93  (via drill 0.6)
  Top 0.813: v56.52,41.59 v89.53,41.59
  Bottom 0.813: JP5.5 69.31,25.5 68.58,24.77 57.15,24.77 56.52,25.4 v56.52,41.59 | v89.53,41.59 92.71,41.59 93.66,42.55 93.66,47.94 116.2,70.48 JP14A.9
COLUMN94  (via drill 0.6)
  Top 0.813: v54.29,39.05 v89.53,39.05
  Bottom 0.813: JP5.7 71.85,23.91 71.12,23.18 54.93,23.18 54.29,23.81 v54.29,39.05 | v89.53,39.05 94.61,39.05 95.57,40.01 95.57,47.62 115.89,67.94 JP14A.10
COLUMN95  (via drill 0.6)
  Top 0.813: v52.07,36.51 v89.53,36.51
  Bottom 0.813: JP5.9 74.39,22.64 73.66,21.91 53.02,21.91 52.07,22.86 v52.07,36.51 | v89.53,36.51 96.52,36.51 97.47,37.47 97.47,47.31 115.57,65.41 JP14A.11
COLUMN96  (via drill 0.6)
  Top 0.813: v49.85,33.97 v89.53,33.97
  Bottom 0.813: JP5.11 76.93,21.37 76.2,20.64 50.48,20.64 49.85,21.27 v49.85,33.97 | v89.53,33.97 98.42,33.97 99.38,34.92 99.38,46.99 115.25,62.87 JP14A.12
COLUMN97  (via drill 0.6)
  Top 0.813: v94.93,20.95 v105.09,20.95
  Bottom 0.813: v105.09,20.95 JP15B.5 | JP5.13 79.47,21.81 80.33,20.95 v94.93,20.95
COLUMN98  (via drill 0.6)
  Top 0.813: v94.93,23.18 v102.55,23.18
  Bottom 0.813: v102.55,23.18 JP15B.6 | JP5.15 82.01,24.04 82.87,23.18 v94.93,23.18
COLUMN99  (via drill 0.6)
  Top 0.813: v94.93,25.4 v100.01,25.4
  Bottom 0.813: v100.01,25.4 JP15B.7 | JP5.17 84.55,25.94 85.09,25.4 v94.93,25.4
COLUMN100
  Bottom 0.813: JP5.19 97.03,28.7 97.47,28.26 JP15B.8
GND  (via drill 0.6, 0.6 pad 0.25)
  Top 0.406: v13.97,93.66 v17.46,93.66 | v9.84,43.5 v13.97,43.5
  Top 1.016: v89.53,226.69 v61.59,226.69 | v97.47,134.3 v49.85,134.3
  Bottom 0.406: JP9.12 24.13,66.21 22.54,64.77 21.27,63.5 21.27,54.29 21.91,53.66 IC1.13 27.62,53.66 28.26,53.02 28.26,40.96 | JP9.11 15.01,70.72 13.97,71.75 v13.97,93.66 | v17.46,93.66 23.34,93.66 JP9.2 | v13.97,43.5 IC1.8 | v9.84,43.5 9.84,41.27 11.43,39.69 13.65,39.69 13.76,39.58
  Bottom 0.61: 28.26,40.64 28.26,40.96 R3.1 | JP13B.1 R1.1
  Bottom 0.813: JP14B.1 R2.1 | 13.92,13.34 X2.5 | 31.43,13.34 R5.1
  Bottom 1.016: v61.59,226.69 61.59,230.5 60.96,231.14 38.1,231.14 37.47,231.78 JP11B.1 | v89.53,226.69 89.53,231.14 90.17,231.78 JP12B.1 126.36,231.78 127.64,230.5 127.64,145.41 125.73,143.51 120.65,143.51 120.02,142.88 R2.1 JP14B.1 120.65,131.44 | JP9.12 JP9.11 | 28.26,40.64 27.3,39.69 13.65,39.69 | 120.65,131.44 125.73,131.44 127.95,129.22 127.95,45.4 123.51,40.96 R4.1 116.2,40.96 115.25,40.01 JP15B.1 115.25,13.34 114.62,12.7 98.74,12.7 97.79,11.75 97.79,8.26 96.52,6.99 45.09,6.99 44.13,7.94 44.13,12.38 43.18,13.34 31.43,13.34 13.92,13.34 | X2.5 10.32,13.5 9.21,14.61 9.21,32.07 10.48,33.34 13.59,33.34 X2.1 13.76,39.58 | JP13B.1 46.99,131.44 v49.85,134.3 | v97.47,134.3 107.95,134.3 110.81,131.44 120.65,131.44
N$1  (via drill 0.6 pad 0.25)
  Top 0.813: v51.44,173.35 v51.44,160.66
  Bottom 0.61: v51.44,173.35 51.44,184.15 87,219.71 89.22,219.71 91.12,221.62 94.61,221.62 97.16,224.16 JP12B.4
  Bottom 0.813: v51.44,160.66 JP11A.13
N$2  (via drill 0.6 pad 0.25)
  Top 0.813: v95.25,140.97 v69.53,140.97
  Bottom 0.813: JP12A.13 117.47,160.66 97.79,140.97 v95.25,140.97 | JP13B.4 46.04,123.83 63.18,140.97 v69.53,140.97
N$3  (via drill 0.6 pad 0.25)
  Top 0.813: v56.52,123.83 v86.68,123.83 | v53.34,60.33 v53.34,120.65
  Bottom 0.813: v86.68,123.83 JP14B.4 | v56.52,123.83 54.29,123.83 53.34,122.87 v53.34,120.65 | JP13A.13 v53.34,60.33
N$4
  Bottom 0.406: JP14A.13 114.3,60.33 107.63,53.66 JP15B.4
N$5
  Bottom 0.813: Q1.S JP8.1
N$6
  Bottom 0.813: Q2.S 19.05,234.31 20.32,235.59 20.32,240.35 26.99,247.01 JP8.2
N$7
  Bottom 0.813: Q3.S 20.32,219.07 21.59,220.34 21.59,239.4 29.53,247.01 JP8.3
N$8
  Bottom 0.813: Q4.S 19.05,203.84 20.32,205.1 20.32,214.31 22.86,216.85 22.86,238.44 30.48,245.75 30.8,245.75 32.07,247.01 JP8.4
N$9
  Bottom 0.813: Q5.S 18.73,188.59 19.68,189.55 19.68,197.17 21.59,199.07 21.59,213.68 24.13,216.22 24.13,237.49 32.07,245.11 33.34,245.11 34.61,246.38 JP8.5
N$10
  Bottom 0.813: Q6.S 18.41,173.35 19.05,173.99 19.05,182.56 20.95,184.47 20.95,196.53 22.86,198.44 22.86,213.04 25.4,215.58 25.4,236.54 32.7,243.52 35.88,243.52 37.15,244.79 JP8.6
N$11  (via drill 0.6)
  Top 0.406: v26.67,56.2 v26.67,65.09
  Bottom 0.406: JP9.10 26.44,73.26 26.99,72.71 26.99,67.31 26.67,66.99 v26.67,65.09 | IC1.14 v26.67,56.2
N$12
  Bottom 0.813: Q7.S 20,158.12 20.64,158.75 20.64,182.25 22.23,183.83 22.23,195.9 24.13,197.8 24.13,212.41 26.67,214.95 26.67,235.59 33.34,241.94 36.83,241.94 39.69,244.79 JP8.7
N$13
  Bottom 0.813: Q8.S 18.41,142.88 19.05,143.51 19.05,152.72 21.91,155.57 21.91,181.61 23.5,183.2 23.5,195.26 25.4,197.17 25.4,211.77 27.94,214.31 27.94,234.63 33.97,240.35 37.15,240.35 42.23,245.43 JP8.8
N$14
  Bottom 0.813: Q9.S 19.68,127.64 20.64,128.59 20.64,152.4 23.18,154.94 23.18,180.97 24.77,182.56 24.77,194.63 26.67,196.53 26.67,211.14 29.21,213.68 29.21,233.36 34.61,238.76 37.78,238.76 44.77,245.75 JP8.9
N$15
  Bottom 0.813: Q10.S 21.91,112.39 22.54,113.03 22.54,152.4 24.45,154.31 24.45,180.34 26.04,181.93 26.04,193.99 27.94,195.9 27.94,210.5 30.48,213.04 30.48,232.41 35.24,237.17 38.42,237.17 47.31,246.06 JP8.10
N$16  (via drill 0.6 pad 0.25)
  Top 0.406: v6.99,56.2 v13.97,56.2
  Bottom 0.406: Q1.G 13.97,240.66 10.79,237.49 10.79,224.16 9.84,223.2 9.84,209.55 8.89,208.6 8.89,195.58 7.94,194.63 7.94,181.29 6.99,180.34 6.99,165.74 6.03,164.78 6.03,151.13 5.08,150.18 5.08,136.53 4.13,135.57 4.13,121.92 3.17,120.97 3.17,56.83 3.81,56.2 v6.99,56.2 | v13.97,56.2 IC1.3
N$17  (via drill 0.6 pad 0.25)
  Top 0.406: v6.99,58.74 v13.97,58.74
  Bottom 0.406: Q2.G 13.97,225.74 10.79,222.57 10.79,208.91 9.84,207.96 9.84,194.94 8.89,193.99 8.89,180.66 7.94,179.71 7.94,165.1 6.99,164.15 6.99,150.5 6.03,149.54 6.03,135.89 5.08,134.94 5.08,121.28 4.13,120.33 4.13,59.37 4.76,58.74 v6.99,58.74 | v13.97,58.74 IC1.2
N$18  (via drill 0.6 pad 0.25)
  Top 0.406: v6.99,53.66 v13.97,53.66
  Bottom 0.406: Q3.G 13.97,210.5 10.79,207.33 10.79,194.31 9.84,193.36 9.84,180.02 8.89,179.07 8.89,164.47 7.94,163.51 7.94,149.86 6.99,148.91 6.99,135.25 6.03,134.3 6.03,120.65 5.08,119.7 5.08,60.96 5.71,60.33 7.94,60.33 8.57,59.69 8.57,54.29 7.94,53.66 v6.99,53.66 | v13.97,53.66 IC1.4
N$19  (via drill 0.6 pad 0.25)
  Top 0.406: v9.84,46.04 v13.97,46.04
  Bottom 0.406: Q4.G 13.97,195.26 10.79,192.09 10.79,179.39 9.84,178.44 9.84,163.83 8.89,162.88 8.89,149.22 7.94,148.27 7.94,134.62 6.99,133.67 6.99,120.02 6.03,119.06 6.03,61.91 6.67,61.28 8.89,61.28 9.53,60.64 9.53,53.66 8.89,53.02 8.89,49.85 9.84,48.9 v9.84,46.04 | v13.97,46.04 IC1.7
N$20
  Bottom 0.406: Q5.G 13.97,180.02 10.79,176.85 10.79,163.19 9.84,162.24 9.84,148.59 8.89,147.64 8.89,133.99 7.94,133.03 7.94,119.38 6.99,118.43 6.99,62.87 7.62,62.23 9.84,62.23 10.48,61.59 10.48,53.02 9.84,52.39 9.84,50.16 11.43,48.58 11.43,41.59 12.06,40.96 26.67,40.96 27.3,41.59 27.3,45.4 26.67,46.04 IC1.10
N$21  (via drill 0.6 pad 0.25)
  Top 0.406: v9.84,63.82 v16.51,63.82
  Bottom 0.406: Q6.G 13.97,164.78 10.79,161.61 10.79,147.96 9.84,147 9.84,133.35 8.89,132.4 8.89,118.75 7.94,117.79 7.94,64.45 8.57,63.82 v9.84,63.82 | v16.51,63.82 IC1.1
N$22  (via drill 0.6 pad 0.25)
  Top 0.406: v11.43,51.12 v13.97,51.12
  Bottom 0.406: Q7.G 13.97,149.54 10.79,146.37 10.79,132.72 9.84,131.76 9.84,118.11 8.89,117.16 8.89,66.67 9.53,66.04 10.79,66.04 11.43,65.41 v11.43,51.12 | v13.97,51.12 IC1.5
N$23
  Bottom 0.406: Q8.G 13.97,134.3 10.79,131.13 10.79,117.47 9.84,116.52 9.84,67.63 10.48,66.99 12.06,66.99 12.7,66.36 12.7,49.21 13.34,48.58 IC1.6
N$24
  Bottom 0.406: Q9.G 13.97,119.06 10.79,115.89 10.79,68.58 11.43,67.94 14.29,67.94 14.92,67.31 14.92,66.67 16.19,65.41 18.41,65.41 19.37,64.45 19.37,44.13 20,43.5 IC1.9
N$25
  Bottom 0.406: Q10.G 13.97,106.68 12.06,104.78 12.06,69.53 12.7,68.9 15.56,68.9 16.19,68.26 16.19,66.99 16.83,66.36 19.05,66.36 20.32,65.09 20.32,49.21 20.95,48.58 IC1.11
N$26
  Bottom 0.813: JP7.1 JP15B.9
N$27  (via drill 0.6)
  Top 0.406: v21.27,107 v21.27,103.5
  Bottom 0.406: JP11B.4 32.38,224.16 31.75,223.52 31.75,212.41 29.21,209.87 29.21,195.26 27.3,193.36 27.3,181.61 25.72,180.02 25.72,153.99 23.81,152.08 23.81,112.71 21.27,110.17 v21.27,107 | JP9.7 23.98,80.96 16.83,80.96 15.88,81.92 15.88,97.16 21.27,102.55 v21.27,103.5
N$28
  Bottom 0.813: JP7.2 JP15B.10
N$29
  Bottom 0.813: JP7.3 JP15B.11
N$30
  Bottom 0.813: JP11A.15 32.07,155.57 31.11,154.62 31.11,148.59 31.75,147.96 R1.2
N$31
  Bottom 0.813: JP12A.15 118.11,155.57 117.47,154.94 113.98,154.94 113.35,154.31 113.35,148.59 113.98,147.96 R2.2
N$32
  Bottom 0.813: JP13A.15 37.78,55.24 38.42,54.61 38.42,49.53 37.47,48.58 R3.2
N$33
  Bottom 0.61: JP14A.15 110.81,55.24 109.22,53.66 109.22,49.53 110.17,48.58 R4.2
N$34
  Bottom 0.406: 39.05,21.38 R5.2
  Bottom 0.813: JP15A.15 39.05,21.38
N$35
  Bottom 0.813: JP7.4 JP15B.12
N$36
  Bottom 0.813: JP7.5 JP15B.13
N$37
  Bottom 0.813: JP7.6 JP15B.14
N$38  (via drill 0.6)
  Top 0.406: v27.94,58.74 v27.94,62.87
  Bottom 0.406: JP9.9 27.39,75.8 28.26,74.93 28.26,64.14 27.94,63.82 v27.94,62.87 | IC1.15 v27.94,58.74
N$39
  Bottom 0.813: JP7.7 JP15B.15
N$40
  Bottom 0.813: JP7.8 JP15B.16
N$41
  Bottom 0.813: JP7.9 JP15A.1
N$42
  Bottom 0.813: JP7.10 JP15A.2
N$43
  Bottom 0.813: JP7.11 JP15A.3
N$44
  Bottom 0.813: JP7.12 JP15A.4
N$45
  Bottom 0.813: JP7.13 JP15A.5
N$46
  Bottom 0.813: JP7.14 JP15A.6
N$47
  Bottom 0.813: JP7.15 JP15A.7
N$48
  Bottom 0.813: JP7.16 JP15A.8
N$49
  Bottom 0.813: JP7.17 JP15A.9
N$50
  Bottom 0.813: JP7.18 JP15A.10
N$51
  Bottom 0.813: JP7.19 JP15A.11
N$52
  Bottom 0.813: JP7.20 JP15A.12
N$53
  Bottom 0.813: JP6.1 64.23,252.19 JP10.1
N$54
  Bottom 0.813: JP6.2 66.77,252.19 JP10.2
N$55
  Bottom 0.813: JP6.3 69.31,252.19 JP10.3
N$56
  Bottom 0.813: JP6.4 71.85,252.19 JP10.4
N$57
  Bottom 0.813: JP6.5 74.39,252.19 JP10.5
N$58
  Bottom 0.813: JP6.6 76.93,252.19 JP10.6
N$59
  Bottom 0.813: JP6.7 79.47,252.19 JP10.7
N$60
  Bottom 0.813: JP6.8 82.01,252.19 JP10.8
N$61
  Bottom 0.813: JP6.9 84.55,252.19 JP10.9
N$62
  Bottom 0.813: JP6.10 87.09,252.19 JP10.10
N$63
  pour Bottom: 0.32,260.67 130.81,260.99 130.81,0 0.32,0
XLAT  (via drill 0.6, 0.6 pad 0.25)
  Top 0.406: v114.3,57.78 v68.26,57.78 | v31.11,78.42 v27.62,78.42 | v123.83,148.27 v123.83,124.14
  Top 0.813: v115.89,156.53 v84.45,156.53
  Bottom 0.406: v68.26,57.78 66.04,57.78 | 66.04,57.78 JP13A.14 32.07,57.78 31.11,58.74 v31.11,78.42 | v114.3,57.78 JP14A.14 123.51,57.78 124.14,58.42 124.14,121.92 123.83,122.24 v123.83,124.14 | JP9.8 27.39,78.34 27.39,78.42 v27.62,78.42 | v123.83,148.27 123.83,157.48 123.19,158.12 JP12A.14 | JP15A.14 41.59,31.75 66.04,56.2 66.04,57.78
  Bottom 0.813: v84.45,156.53 82.87,158.12 JP11A.14 35.88,158.12 | v115.89,156.53 117.47,158.12 JP12A.14

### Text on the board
Bottom: http://libesz.digitaltrip.hu | Fade Cube board #2 | 2010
